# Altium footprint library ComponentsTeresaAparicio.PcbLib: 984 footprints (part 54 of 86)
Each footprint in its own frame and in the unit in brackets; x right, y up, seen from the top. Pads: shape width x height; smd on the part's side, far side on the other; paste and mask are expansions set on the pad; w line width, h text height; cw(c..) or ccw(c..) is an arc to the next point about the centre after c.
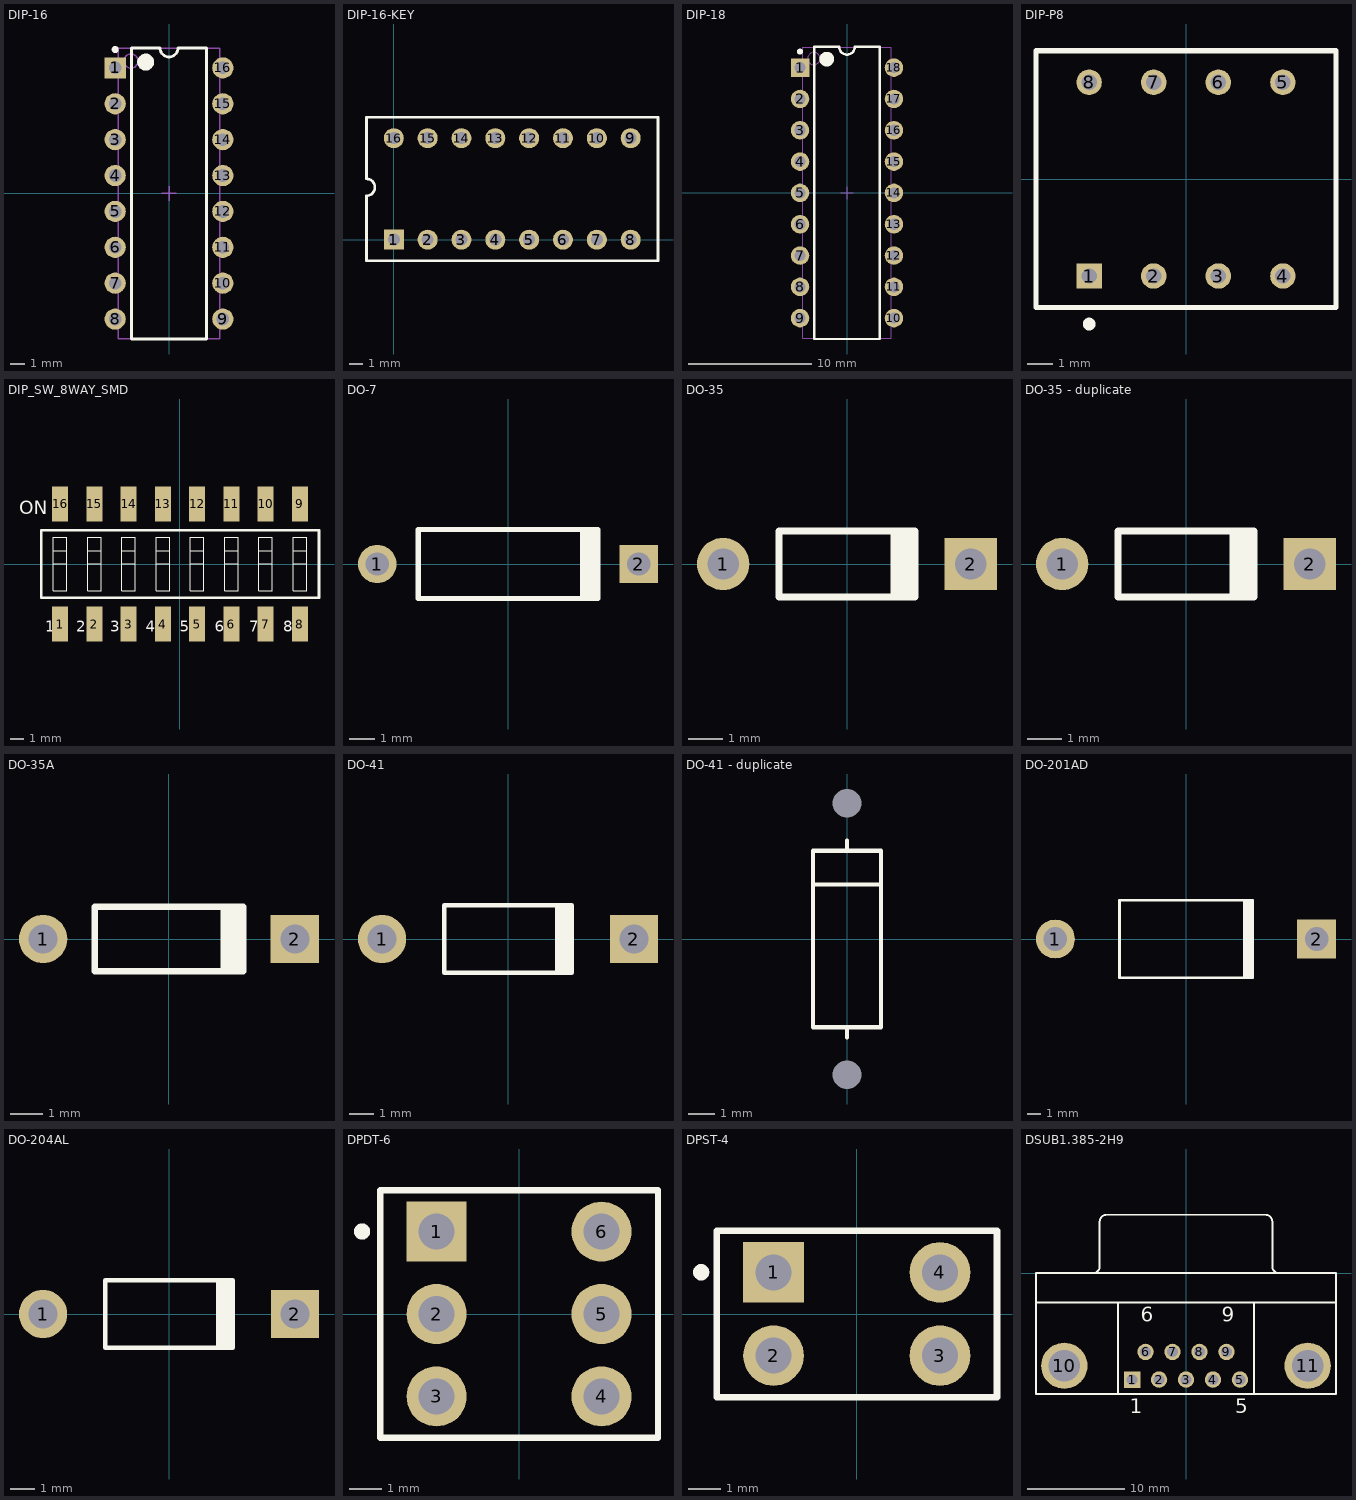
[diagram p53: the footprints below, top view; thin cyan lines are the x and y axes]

## DIP-16 [mm] "DIP; 16 Leads; Row Spacing 7.62 mm; Pitch 2.54 mm"
height 5.08
pads (16):
  rect 1.5x1.5 hole 0.9: 1(-3.81,8.89)
  round 1.5 hole 0.9: 2(-3.81,6.35) 3(-3.81,3.81) 4(-3.81,1.27) 5(-3.81,-1.27) 6(-3.81,-3.81) 7(-3.81,-6.35) 8(-3.81,-8.89) 9(3.81,-8.89) 10(3.81,-6.35) 11(3.81,-3.81) 12(3.81,-1.27) 13(3.81,1.27) 14(3.81,3.81) 15(3.81,6.35) 16(3.81,8.89)
Top Overlay:
  circle w0.25: c-3.81,10.19 r0.125
  circle w0.6: c-1.65,9.3 r0.3
  lines w0.2: -2.65,-10.3 -2.65,10.3 -0.635,10.3 ccw(c0,10.3) 0.635,10.3 2.65,10.3 2.65,-10.3 -2.65,-10.3
Mechanical 13:
  circle w0.1: c-2.7,9.375 r0.5
  lines w0.1: -3.6,-10.275 -3.6,10.275 3.6,10.275 3.6,-10.275 -3.6,-10.275
Mechanical 15:
  lines w0.1: -0.5,0 0.5,0 ; 0,-0.5 0,0.5
3D body: height 5.08, standoff 0, extent -3.6,-10.275 3.6,10.275

## DIP-16-KEY [mm] "DIP; 16 Leads; Row Spacing 7.62 mm; Pitch 2.54 mm"
pads (16):
  rect 1.5x1.5 hole 0.9: 1(0,0)
  round 1.5 hole 0.9: 2(2.54,0) 3(5.08,0) 4(7.62,0) 5(10.16,0) 6(12.7,0) 7(15.24,0) 8(17.78,0) 9(17.78,7.62) 10(15.24,7.62) 11(12.7,7.62) 12(10.16,7.62) 13(7.62,7.62) 14(5.08,7.62) 15(2.54,7.62) 16(0,7.62)
Top Overlay:
  lines w0.2: -2.05,4.57 cw(c-2.05,3.935) -2.05,3.3 -2.05,-1.59 19.83,-1.59 19.83,9.2 -2.05,9.2 -2.05,4.6

## DIP-18 [mm] "DIP; 18 Leads; Row Spacing 7.62 mm; Pitch 2.54 mm"
height 5.08
pads (18):
  rect 1.5x1.5 hole 0.9: 1(-3.81,10.16)
  round 1.5 hole 0.9: 2(-3.81,7.62) 3(-3.81,5.08) 4(-3.81,2.54) 5(-3.81,0) 6(-3.81,-2.54) 7(-3.81,-5.08) 8(-3.81,-7.62) 9(-3.81,-10.16) 10(3.81,-10.16) 11(3.81,-7.62) 12(3.81,-5.08) 13(3.81,-2.54) 14(3.81,0) 15(3.81,2.54) 16(3.81,5.08) 17(3.81,7.62) 18(3.81,10.16)
Top Overlay:
  circle w0.25: c-3.81,11.46 r0.125
  circle w0.6: c-1.65,10.85 r0.3
  lines w0.2: -2.65,-11.85 -2.65,11.85 -0.635,11.85 ccw(c0,11.85) 0.635,11.85 2.65,11.85 2.65,-11.85 -2.65,-11.85
Mechanical 13:
  circle w0.1: c-2.7,10.9 r0.5
  lines w0.1: -3.6,-11.8 -3.6,11.8 3.6,11.8 3.6,-11.8 -3.6,-11.8
Mechanical 15:
  lines w0.1: -0.5,0 0.5,0 ; 0,-0.5 0,0.5
3D body: height 5.08, standoff 0, extent -3.6,-11.8 3.6,11.8

## DIP-P8 [mm] "Dual-Pole Dual-Throw Relay; 8 Leads"
pads (8):
  rect 1x1 hole 0.6: 1(-3.81,-3.81)
  round 1 hole 0.6: 2(-1.27,-3.81) 3(1.27,-3.81) 4(3.81,-3.81) 5(3.81,3.81) 6(1.27,3.81) 7(-1.27,3.81) 8(-3.81,3.81)
Top Overlay:
  circle w0.25: c-3.81,-5.7 r0.125
  lines w0.2: -5.9,-5.05 5.9,-5.05 5.9,5.05 -5.9,5.05 -5.9,-0.635 -5.9,-5.05

## DIP_SW_8WAY_SMD [mm] "DIP Switch; 16 Leads"
height 5.06
pads (16):
  rect 1.2x2.6 smd: 1(-8.89,-4.45) 2(-6.35,-4.45) 3(-3.81,-4.45) 4(-1.27,-4.45) 5(1.27,-4.45) 6(3.81,-4.45) 7(6.35,-4.45) 8(8.89,-4.45) 9(8.89,4.45) 10(6.35,4.45) 11(3.81,4.45) 12(1.27,4.45) 13(-1.27,4.45) 14(-3.81,4.45) 15(-6.35,4.45) 16(-8.89,4.45)
Top Overlay:
  lines w0.025: -9.39,0 -8.39,0 ; -9.39,1 -8.39,1 ; -6.85,0 -5.85,0 ; -6.85,1 -5.85,1 ; -4.31,0 -3.31,0 ; -4.31,1 -3.31,1 ; -1.77,0 -0.77,0 ; -1.77,1 -0.77,1 ; 0.77,0 1.77,0 ; 0.77,1 1.77,1 ; 3.31,0 4.31,0 ; 3.31,1 4.31,1 ; 5.85,0 6.85,0 ; 5.85,1 6.85,1 ; 8.39,0 9.39,0 ; 8.39,1 9.39,1 ; -9.39,-2 -8.39,-2 -8.39,2 -9.39,2 -9.39,-2 ; -6.85,-2 -5.85,-2 -5.85,2 -6.85,2 -6.85,-2 ; -4.31,-2 -3.31,-2 -3.31,2 -4.31,2 -4.31,-2 ; -1.77,-2 -0.77,-2 -0.77,2 -1.77,2 -1.77,-2 ; 0.77,-2 1.77,-2 1.77,2 0.77,2 0.77,-2 ; 3.31,-2 4.31,-2 4.31,2 3.31,2 3.31,-2 ; 5.85,-2 6.85,-2 6.85,2 5.85,2 5.85,-2 ; 8.39,-2 9.39,-2 9.39,2 8.39,2 8.39,-2
  lines w0.2: -10.29,-2.5 10.31,-2.5 10.31,2.5 -10.29,2.5 -10.29,-2.5
  text "8" at 7.659,-5.032 h0.8
  text "7" at 5.119,-5.032 h0.8
  text "ON" at -11.938,3.678 h1
  text "1" at -10.006,-5.032 h0.8
  text "2" at -7.681,-5.032 h0.8
  text "3" at -5.181,-5.032 h0.8
  text "4" at -2.556,-5.032 h0.8
  text "5" at -0.031,-5.032 h0.8
  text "6" at 2.569,-5.032 h0.8

## DO-7 [mm] "Diode, Axial; Body 7 x 2.7 mm (LxDia. max), Lead Dia. 0.53 mm (max)"
height 2.7
pads (2):
  round 1.5 hole 0.9: 1(-5.1,0)
  rect 1.5x1.5 hole 0.9: 2(5.1,0)
Top Overlay:
  rectangle: 2.8,-1.35 3.6,1.35
  lines w0.2: 3.5,-1.35 -3.5,-1.35 -3.5,1.35 3.5,1.35

## DO-35 [mm] "Diode, Axial; Body 3.8 x 1.9 mm (LxDia. max), Lead Dia. 0.53 mm (max)"
height 1.9
pads (2):
  round 1.5 hole 0.9: 1(-3.55,0)
  rect 1.5x1.5 hole 0.9: 2(3.55,0)
Top Overlay:
  rectangle: 1.25,-0.95 2.05,0.95
  lines w0.2: 1.95,-0.95 -1.95,-0.95 -1.95,0.95 1.95,0.95

## DO-35 - duplicate [mm] "Diode, Axial; Body 3.8 x 1.9 mm (LxDia. max), Lead Dia. 0.53 mm (max)"
height 1.9
pads (2):
  round 1.5 hole 0.9: 1(-3.55,0)
  rect 1.5x1.5 hole 0.9: 2(3.55,0)
Top Overlay:
  rectangle: 1.25,-0.95 2.05,0.95
  lines w0.2: 1.95,-0.95 -1.95,-0.95 -1.95,0.95 1.95,0.95
3D body: height 3, standoff -3.5, extent -3.75,-0.889 3.75,1.111

## DO-35A [mm] "Diode, Axial; Body 4.6 x 1.9 mm (LxDia. max), Lead Dia. 0.53 mm (max)"
height 2
pads (2):
  round 1.5 hole 0.9: 1(-3.9,0)
  rect 1.5x1.5 hole 0.9: 2(3.9,0)
Top Overlay:
  rectangle: 1.6,-1 2.4,1
  lines w0.2: 2.3,-1 -2.3,-1 -2.3,1 2.3,1

## DO-41 [mm] "Diode, Axial; Body 5.2 x 2.7 mm (LxDia. max), Lead Dia. 0.86 mm (max)"
height 2.8
pads (2):
  round 2 hole 1.2: 1(-5.23,0)
  rect 2x2 hole 1.2: 2(5.23,0)
Top Overlay:
  rectangle: 1.95,-1.4 2.75,1.4
  lines w0.2: 2.65,-1.4 -2.65,-1.4 -2.65,1.4 2.65,1.4

## DO-41 - duplicate [mil] "Diode, thru-hole"
height 106.3
pads (2):
  round 0 / inner round 0 / far side round 100 hole 42 unplated: A(0,-200) K(0,200)
Top Overlay:
  lines w6: -50,80 50,80 ; 0,-145 0,-130 ; 0,130 0,145 ; -50,-130 -50,130 50,130 50,-130 -50,-130
3D body: height 100.5, standoff -100, extent -51,-215 50,215

## DO-201AD [mm] "Diode, Axial; Body 9.5 x 5.6 mm (LxDia. max), Lead Dia. 1.32 mm (max)"
height 5.6
pads (2):
  round 2.8 hole 1.7: 1(-9.42,0)
  rect 2.8x2.8 hole 1.7: 2(9.42,0)
Top Overlay:
  rectangle: 4.1,-2.8 4.9,2.8
  lines w0.2: 4.8,-2.8 -4.8,-2.8 -4.8,2.8 4.8,2.8

## DO-204AL [mm] "Diode, Axial; Body 5.2 x 2.7 mm (LxDia. max), Lead Dia. 0.86 mm (max)"
height 2.7
pads (2):
  round 2 hole 1.2: 1(-5.23,0)
  rect 2x2 hole 1.2: 2(5.23,0)
Top Overlay:
  rectangle: 1.95,-1.4 2.75,1.4
  lines w0.2: 2.65,-1.4 -2.65,-1.4 -2.65,1.4 2.65,1.4

## DPDT-6 [mm] "Switch; 6 Leads"
pads (6):
  rect 1.85x1.85 hole 1.1: 1(-2.54,2.54)
  round 1.85 hole 1.1: 2(-2.54,0) 3(-2.54,-2.54) 4(2.54,-2.54) 5(2.54,0) 6(2.54,2.54)
Top Overlay:
  circle w0.25: c-4.836,2.541 r0.125
  lines w0.2: -4.28,-3.81 4.28,-3.81 4.28,3.81 -4.28,3.81 -4.28,-3.81

## DPST-4 [mm] "Switch; 4 Leads"
pads (4):
  rect 1.85x1.85 hole 1.1: 1(-2.54,1.27)
  round 1.85 hole 1.1: 2(-2.54,-1.27) 3(2.54,-1.27) 4(2.54,1.27)
Top Overlay:
  circle w0.25: c-4.751,1.274 r0.125
  lines w0.2: -4.28,-2.54 -4.28,2.54 4.28,2.54 4.28,-2.54 -4.28,-2.54

## DSUB1.385-2H9 [mm] "Connector; D Subminiature; 9 Position; Right Angle; Pitch 1.385 mm"
height 12.75
pads (11):
  rect 1.69x1.69 hole 1.09: 1(-5.54,-10.92)
  round 1.69 hole 1.09: 2(-2.77,-10.92) 3(0,-10.92) 4(2.77,-10.92) 5(5.54,-10.92) 6(-4.155,-8.08) 7(-1.385,-8.08) 8(1.385,-8.08) 9(4.155,-8.08)
  round 4.76 hole 3.26: 10(-12.495,-9.5) 11(12.495,-9.5)
Top Overlay:
  lines w0.2: -15.4,-3 15.4,-3 ; -9.56,0.005 ccw(c-9.56,0.7) -8.865,0.7 -8.865,5.3 ; -8.86,5.305 cw(c-8.165,5.305) -8.165,6 8.165,6 cw(c8.165,5.305) 8.86,5.305 ; -7,-12.4 -7,-3 ; 7,-12.4 7,-3 ; 8.865,5.3 8.865,0.7 ccw(c9.56,0.7) 9.56,0.005 ; -15.4,-12.4 -15.4,0 15.4,0 15.4,-12.4 -15.4,-12.4
  text "1" at -5.79,-14.375 h1.5
  text "5" at 5.04,-14.375 h1.5
  text "9" at 3.655,-4.975 h1.5
  text "6" at -4.655,-4.975 h1.5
